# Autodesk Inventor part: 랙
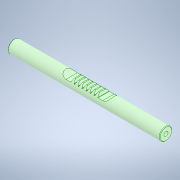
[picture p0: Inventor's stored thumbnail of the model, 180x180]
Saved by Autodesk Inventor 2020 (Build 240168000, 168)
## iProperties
Created: 2024-05
Part Number: 랙
Material: 강철, 탄소
Document SubType Name: Modeling
Designer: oem
Density: 7.85 g/cm^3
Appearance: 기본값
Author: jhkim
Sending System: Autodesk Inventor 2025
Preprocessor: ST-DEVELOPER v20
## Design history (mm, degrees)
feature "솔리드1"
node "솔리드2"
